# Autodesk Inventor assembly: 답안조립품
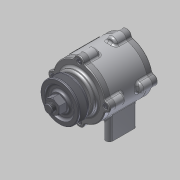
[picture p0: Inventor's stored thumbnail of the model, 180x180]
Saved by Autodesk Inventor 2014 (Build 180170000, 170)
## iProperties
Created: 2015-03
Part Number: 답안조립품
Document SubType Name: Assembly
Designer: MYHOME
Author: MYHOME
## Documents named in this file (11)
- C:\Documents and Settings\MYHOME\바탕 화면\450306V1009\답안조립품.iam
- C:\Documents and Settings\MYHOME\바탕 화면\450306V1009\본체.ipt
- C:\Documents and Settings\MYHOME\바탕 화면\450306V1009\커버2.ipt
- C:\Documents and Settings\MYHOME\바탕 화면\450306V1009\M 4 x 12.ipt
- C:\Documents and Settings\MYHOME\바탕 화면\450306V1009\커버.ipt
- C:\Documents and Settings\MYHOME\바탕 화면\450306V1009\축.ipt
- C:\Documents and Settings\MYHOME\바탕 화면\450306V1009\베어링 6204.ipt
- C:\Documents and Settings\MYHOME\바탕 화면\450306V1009\오일실.ipt
- C:\Documents and Settings\MYHOME\바탕 화면\450306V1009\키(4 x 4 x 12).ipt
- C:\Documents and Settings\MYHOME\바탕 화면\450306V1009\V벨트풀리.ipt
- C:\Documents and Settings\MYHOME\바탕 화면\450306V1009\너트 M12x1.25.ipt
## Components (14 placed, 6 different names)
1. KS B 2023 6204 - 20 x 47 x 14:1 — 각도:3
2. KS B 2023 6204 - 20 x 47 x 14:2 — 각도:2
3. KS B 2804 D D - 20 32 8:1
4. KS B 1311 (I) 4 x 4 x 12:1
5. 그루브 풀리1:1
6. KS B 1012 클래스 1 일반 - 미터 M12x1.25:1 — 각도:1
7. KS B 1003 - 미터 M 4 x 12:1
8. KS B 1003 - 미터 M 4 x 12:2
9. KS B 1003 - 미터 M 4 x 12:3
10. KS B 1003 - 미터 M 4 x 12:4
11. KS B 1003 - 미터 M 4 x 12:5
12. KS B 1003 - 미터 M 4 x 12:6
13. KS B 1003 - 미터 M 4 x 12:7
14. KS B 1003 - 미터 M 4 x 12:8
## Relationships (3: Angle 3)
- 각도:1 [Angle]: KS B 1012 클래스 1 일반 - 미터 M12x1.25:1
- 각도:2 [Angle]: KS B 2023 6204 - 20 x 47 x 14:2
- 각도:3 [Angle]: KS B 2023 6204 - 20 x 47 x 14:1
